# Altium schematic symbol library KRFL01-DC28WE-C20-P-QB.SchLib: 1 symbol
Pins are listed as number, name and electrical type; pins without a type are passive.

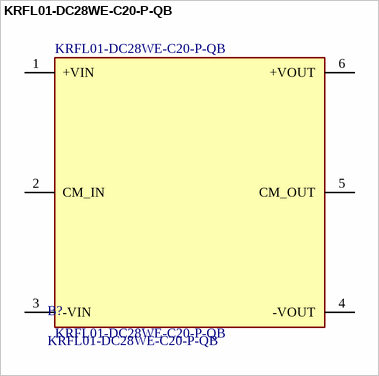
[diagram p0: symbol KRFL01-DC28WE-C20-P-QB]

## KRFL01-DC28WE-C20-P-QB
designator B?
20Aout Passive Quarter EMI Filter Brick; MFG: KOLT
footprint KRFL01-DC28WE-C20-P-QB
pins: 1 +VIN, 2 CM_IN, 3 -VIN, 4 -VOUT, 5 CM_OUT, 6 +VOUT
